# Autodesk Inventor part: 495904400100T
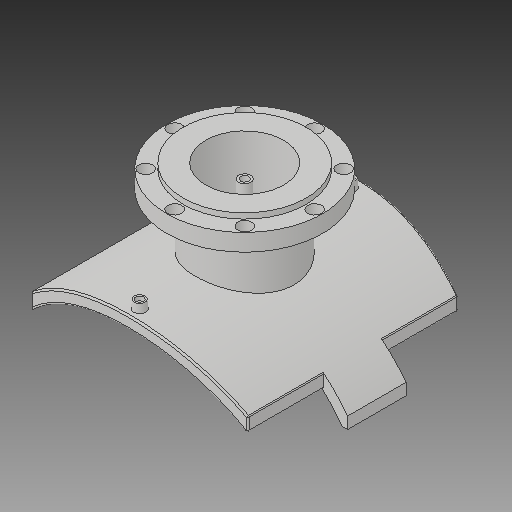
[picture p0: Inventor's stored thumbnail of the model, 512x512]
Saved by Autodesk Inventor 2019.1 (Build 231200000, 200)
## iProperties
Created: 2017-10
Part Number: 495904400100T
Material: Generic
Description: PLASSON FLANGED BRANCH SADDLE 250-400X100
Document SubType Name: Modeling
Designer: KIM
Mass: 2339.99 g
Surface Area: 3251.55 cm^2
Volume: 2339.99 cm^3
Density: 1 g/cm^3
Appearance: Default
Author: KIM
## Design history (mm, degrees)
derived "495904_495903.ipt"
feature "Solid1::495904_495903.ipt"
feature "Solid2::495904_495903.ipt"
tag "TaggingFeature1"
body "Solid1"
other parameters: "d1" = 15, "d2" = 278.1, "d4" = 0, "d6" = 75, "d7" = 0, "d12" = 225.6, "d13" = 14, "d14" = 135, "d16" = 5 deg, "d18" = 4, "d19" = 14, "d20" = 0, "d21" = 3, "d22" = 0, "d23" = 325, "d36" = 135, "d38" = 0, "d39" = 2, "d42" = 158, "d44" = 88, "d46" = 126.4, "d47" = 16, "d48" = 10.4, "d49" = 77, "d51" = 408, "d53" = 0, "d54" = 18, "d57" = 0, "d59" = 360 deg, "d61" = 22, "d63" = 0, "d67" = 15, "d68" = 55, "d70" = 0, "d71" = 2, "d72" = 309, "d_1" = 158, "B_" = 309, "x_" = 15, "D_" = 16, "t_" = 22, "s_" = 18
